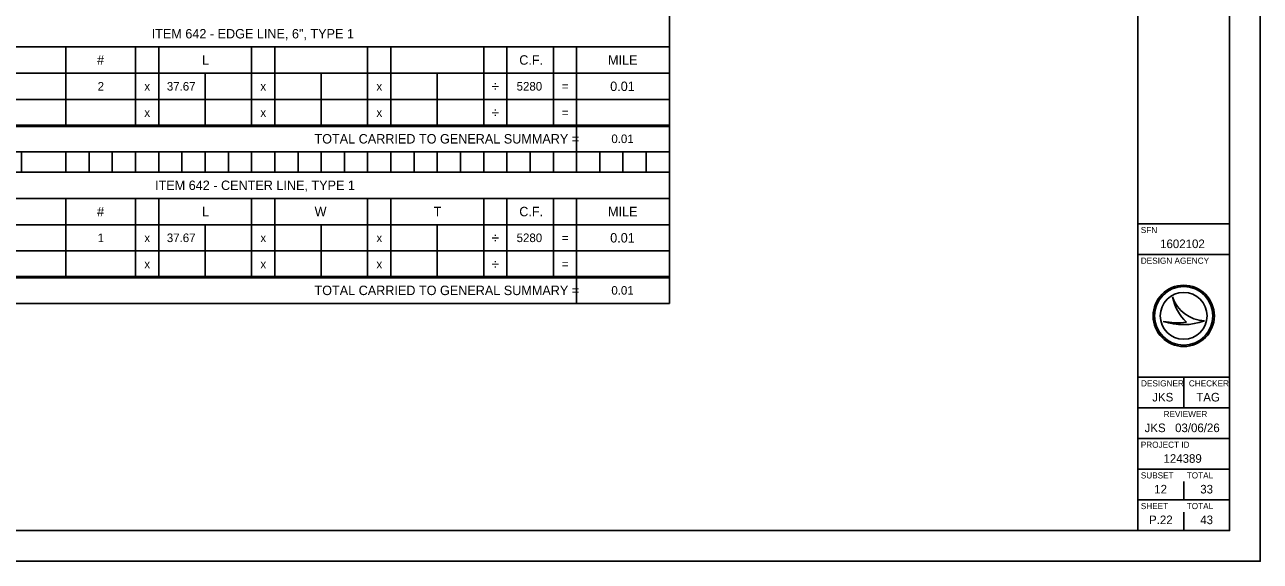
# Model space of a CAD drawing. Extents: x 0 to 34, y 0 to 22.
# Drawn here: x 13.83 to 34, y 0 to 8.75 of the extents above; entities that cross this region are included whole.
import ezdxf

# ---------------------------------------------------------------- set-up
doc = ezdxf.new("R2010")
doc.units = 0
for name, color, linetype in [('Default', 7, 'Continuous'), ('SH_Border', 7, 'Continuous'), ('SH_Cut_Line', 7, 'Continuous'), ('SH_Data', 7, 'Continuous')]:
    doc.layers.add(name, color=color, linetype=linetype)

msp = doc.modelspace()

# ---------------------------------------------------------------- linework, layer by layer
at = {"layer": 'Default'}
for p, q in [((24.356, 9.583), (24.356, 7.09)), ((10.751, 8.386), (24.356, 8.386)), ((14.506, 8.386), (14.506, 7.112)), ((15.643, 8.386), (15.643, 7.112)), ((16.022, 8.386), (16.022, 7.112)), ((17.537, 8.386), (17.537, 7.112)), ((17.916, 8.386), (17.916, 7.112)), ((19.431, 8.386), (19.431, 7.112)), ((19.81, 8.386), (19.81, 7.112)), ((21.325, 8.386), (21.325, 7.112)), ((21.704, 8.386), (21.704, 7.112)), ((22.462, 8.386), (22.462, 7.112)), ((22.841, 8.386), (22.841, 7.112)), ((10.751, 7.957), (24.356, 7.957)), ((16.779, 7.957), (16.779, 7.112)), ((18.673, 7.957), (18.673, 7.112)), ((20.568, 7.957), (20.568, 7.112)), ((10.751, 7.529), (24.356, 7.529)), ((10.751, 7.112), (24.356, 7.112)), ((10.751, 7.09), (24.356, 7.09)), ((22.841, 7.09), (22.841, 6.673)), ((24.356, 7.112), (24.356, 4.619)), ((10.751, 6.673), (24.356, 6.673)), ((10.751, 6.343), (24.356, 6.343)), ((10.751, 5.915), (24.356, 5.915)), ((14.506, 5.915), (14.506, 4.641)), ((15.643, 5.915), (15.643, 4.641)), ((16.022, 5.915), (16.022, 4.641)), ((17.537, 5.915), (17.537, 4.641)), ((17.916, 5.915), (17.916, 4.641)), ((19.431, 5.915), (19.431, 4.641)), ((19.81, 5.915), (19.81, 4.641)), ((21.325, 5.915), (21.325, 4.641)), ((21.704, 5.915), (21.704, 4.641)), ((22.462, 5.915), (22.462, 4.641)), ((22.841, 5.915), (22.841, 4.641)), ((10.751, 5.487), (24.356, 5.487)), ((16.779, 5.487), (16.779, 4.641)), ((18.673, 5.487), (18.673, 4.641)), ((20.568, 5.487), (20.568, 4.641)), ((10.751, 5.059), (24.356, 5.059)), ((10.751, 4.641), (24.356, 4.641)), ((24.356, 4.641), (24.356, 4.202)), ((10.751, 4.619), (24.356, 4.619)), ((22.841, 4.619), (22.841, 4.202)), ((10.751, 4.202), (24.356, 4.202))]:
    msp.add_line(p, q, dxfattribs=at)
for points in [[(13.782, 6.673), (14.506, 6.673), (14.506, 6.343), (13.782, 6.343)], [(14.506, 6.673), (14.885, 6.673), (14.885, 6.343), (14.506, 6.343)], [(14.885, 6.673), (15.264, 6.673), (15.264, 6.343), (14.885, 6.343)], [(15.264, 6.673), (15.643, 6.673), (15.643, 6.343), (15.264, 6.343)], [(15.643, 6.673), (16.022, 6.673), (16.022, 6.343), (15.643, 6.343)], [(16.022, 6.673), (16.401, 6.673), (16.401, 6.343), (16.022, 6.343)], [(16.401, 6.673), (16.779, 6.673), (16.779, 6.343), (16.401, 6.343)], [(16.779, 6.673), (17.158, 6.673), (17.158, 6.343), (16.779, 6.343)], [(17.158, 6.673), (17.537, 6.673), (17.537, 6.343), (17.158, 6.343)], [(17.537, 6.673), (17.916, 6.673), (17.916, 6.343), (17.537, 6.343)], [(17.916, 6.673), (18.295, 6.673), (18.295, 6.343), (17.916, 6.343)], [(18.295, 6.673), (18.673, 6.673), (18.673, 6.343), (18.295, 6.343)], [(18.673, 6.673), (19.052, 6.673), (19.052, 6.343), (18.673, 6.343)], [(19.052, 6.673), (19.431, 6.673), (19.431, 6.343), (19.052, 6.343)], [(19.431, 6.673), (19.81, 6.673), (19.81, 6.343), (19.431, 6.343)], [(19.81, 6.673), (20.189, 6.673), (20.189, 6.343), (19.81, 6.343)], [(20.189, 6.673), (20.568, 6.673), (20.568, 6.343), (20.189, 6.343)], [(20.568, 6.673), (20.946, 6.673), (20.946, 6.343), (20.568, 6.343)], [(20.946, 6.673), (21.325, 6.673), (21.325, 6.343), (20.946, 6.343)], [(21.325, 6.673), (21.704, 6.673), (21.704, 6.343), (21.325, 6.343)], [(21.704, 6.673), (22.083, 6.673), (22.083, 6.343), (21.704, 6.343)], [(22.083, 6.673), (22.462, 6.673), (22.462, 6.343), (22.083, 6.343)], [(22.462, 6.673), (22.841, 6.673), (22.841, 6.343), (22.462, 6.343)], [(22.841, 6.673), (23.219, 6.673), (23.219, 6.343), (22.841, 6.343)], [(23.219, 6.673), (23.598, 6.673), (23.598, 6.343), (23.219, 6.343)], [(23.598, 6.673), (23.977, 6.673), (23.977, 6.343), (23.598, 6.343)], [(23.977, 6.673), (24.356, 6.673), (24.356, 6.343), (23.977, 6.343)]]:
    msp.add_lwpolyline(points, close=True, dxfattribs=at)
at = {"layer": 'SH_Border'}
for p, q in [((32, 0.5), (32, 21.5)), ((32, 5.5), (33.5, 5.5)), ((32, 5), (33.5, 5)), ((32, 3), (33.5, 3)), ((32.75, 3), (32.75, 2.5)), ((32, 2.5), (33.5, 2.5)), ((32, 2), (33.5, 2)), ((32, 1.5), (33.5, 1.5)), ((32, 1), (33.5, 1))]:
    msp.add_line(p, q, dxfattribs=at)
msp.add_lwpolyline([(1.5, 21.5), (33.5, 21.5), (33.5, 0.5), (1.5, 0.5)], close=True, dxfattribs=at)
at = {"layer": 'SH_Cut_Line'}
msp.add_lwpolyline([(0, 0), (34, 0), (34, 22), (0, 22)], close=True, dxfattribs=at)
at = {"layer": 'SH_Data'}
for p, q in [((32.567, 4.31), (32.567, 4.31)), ((32.417, 3.91), (32.417, 3.91)), ((32.75, 4), (32.75, 4)), ((33.087, 3.919), (33.087, 3.919)), ((32.75, 1), (32.75, 1.3)), ((32.375, 0.675), (32.375, 0.675)), ((32.75, 0.5), (32.75, 0.8))]:
    msp.add_line(p, q, dxfattribs=at)
for radius in [0.5, 0.477, 0.477, 0.382]:
    msp.add_circle((32.75, 4), radius, dxfattribs=at)
for centre, radius, start, end in [((33.116, 4.498), 0.58, 198.9257, 198.9319), ((33.347, 4.47), 0.796, 191.6379, 191.6421), ((33.116, 4.498), 0.58, 198.9319, 267.1657), ((33.347, 4.47), 0.796, 191.6421, 226.0947), ((32.739, 4.87), 1.013, 251.4576, 290.0832), ((32.648, 5.154), 1.266, 259.4964, 259.4995), ((32.739, 4.87), 1.013, 251.4527, 251.4576), ((32.648, 5.154), 1.266, 259.4995, 276.6672)]:
    msp.add_arc(centre, radius, start, end, dxfattribs=at)

# ---------------------------------------------------------------- texts
at = {"layer": 'Default'}
for s, height, p in [('ITEM 642 - EDGE LINE, 6", TYPE 1', 0.154, (15.907, 8.523)), ('#', 0.154, (15.016, 8.095)), ('L', 0.154, (16.729, 8.095)), ('C.F.', 0.154, (21.906, 8.095)), ('MILE', 0.154, (23.355, 8.095)), ('2', 0.14, (15.025, 7.673)), ('x', 0.14, (15.787, 7.673)), ('37.67', 0.14, (16.154, 7.673)), ('x', 0.14, (17.681, 7.673)), ('x', 0.14, (19.575, 7.673)), ('÷', 0.168, (21.453, 7.659)), ('5280', 0.14, (21.863, 7.673)), ('=', 0.14, (22.601, 7.673)), ('0.01', 0.154, (23.39, 7.666)), ('x', 0.14, (15.787, 7.245)), ('x', 0.14, (17.681, 7.245)), ('x', 0.14, (19.575, 7.245)), ('÷', 0.168, (21.453, 7.231)), ('=', 0.14, (22.601, 7.245)), ('TOTAL CARRIED TO GENERAL SUMMARY =', 0.154, (18.564, 6.81)), ('0.01', 0.14, (23.409, 6.817)), ('ITEM 642 - CENTER LINE, TYPE 1', 0.154, (15.962, 6.052)), ('#', 0.154, (15.016, 5.624)), ('L', 0.154, (16.729, 5.624)), ('W', 0.154, (18.566, 5.624)), ('T', 0.154, (20.508, 5.624)), ('C.F.', 0.154, (21.906, 5.624)), ('MILE', 0.154, (23.355, 5.624)), ('1', 0.14, (15.025, 5.203)), ('x', 0.14, (15.787, 5.203)), ('37.67', 0.14, (16.154, 5.203)), ('x', 0.14, (17.681, 5.203)), ('x', 0.14, (19.575, 5.203)), ('÷', 0.168, (21.453, 5.189)), ('5280', 0.14, (21.863, 5.203)), ('=', 0.14, (22.601, 5.203)), ('0.01', 0.154, (23.39, 5.196)), ('x', 0.14, (15.787, 4.775)), ('x', 0.14, (17.681, 4.775)), ('x', 0.14, (19.575, 4.775)), ('÷', 0.168, (21.453, 4.761)), ('=', 0.14, (22.601, 4.775)), ('TOTAL CARRIED TO GENERAL SUMMARY =', 0.154, (18.564, 4.339)), ('0.01', 0.14, (23.409, 4.346))]:
    msp.add_text(s, height=height, dxfattribs=at).set_placement(p)
at = {"layer": 'SH_Data'}
for s, height, p in [('SFN', 0.1, (32.05, 5.35)), ('1602102', 0.14, (32.365, 5.105)), ('DESIGN AGENCY', 0.1, (32.05, 4.85)), ('DESIGNER', 0.1, (32.054, 2.85)), ('CHECKER', 0.1, (32.835, 2.85)), ('JKS', 0.14, (32.237, 2.605)), ('TAG', 0.14, (32.955, 2.605)), ('REVIEWER', 0.1, (32.422, 2.35)), ('JKS', 0.14, (32.112, 2.105)), ('03/06/26', 0.14, (32.609, 2.105)), ('PROJECT ID', 0.1, (32.05, 1.85)), ('124389', 0.14, (32.42, 1.605)), ('SUBSET', 0.1, (32.05, 1.35)), ('TOTAL', 0.1, (32.8, 1.35)), ('12', 0.14, (32.269, 1.105)), ('33', 0.14, (33.02, 1.105)), ('SHEET', 0.1, (32.05, 0.85)), ('TOTAL', 0.1, (32.8, 0.85)), ('P.22', 0.14, (32.185, 0.605)), ('43', 0.14, (33.02, 0.605))]:
    msp.add_text(s, height=height, dxfattribs=at).set_placement(p)

doc.saveas('drawing.dxf')
